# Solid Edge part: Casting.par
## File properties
Author: Deepak Maini
Template: Normal.par
Last saved by: CADCIM
Revision: 10
Application: Solid Edge
Accuracy: 0.99
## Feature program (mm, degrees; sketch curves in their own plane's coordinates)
sketch for "unnamed Protrusion 1" plane through (0, 0, 0) normal (0, -1, 0) x-axis (1, 0, 0)
  line (0, 0) -> (0, 0)
  line (-104, 0) -> (104, 0)
  line (104, 0) -> (100, 14)
  line (100, 14) -> (-100, 14)
  line (-100, 14) -> (-104, 0)
  dimension (linear) = 104
  dimension (linear) = 104
extrude "unnamed Protrusion 1" add finite 46 symmetric
sketch for "ExtrudedProtrusion_2" plane through (0, 0, 0) normal (0, 0, 1) x-axis (1, 0, 0)
  line (-48.8569, 23) -> (48.8569, 23)
  arc centre (0, 0) radius 54 from (48.8569, 23) to (48.8569, -23) cw
  line (-48.8569, -23) -> (48.8569, -23)
  arc centre (0, 0) radius 54 from (-48.8569, -23) to (-48.8569, 23) cw
extrude "ExtrudedProtrusion_2" add finite 68 along +normal
sketch for "ExtrudedCutout_1" plane through (0, 0, 0) normal (0, -1, 0) x-axis (1, 0, 0)
  line (24, 52) -> (24, 48)
  line (28, 52) -> (24, 52)
  line (28, 68) -> (28, 52)
  line (-28, 68) -> (28, 68)
  line (-28, 52) -> (-28, 68)
  line (-24, 52) -> (-28, 52)
  line (-24, 48) -> (-24, 52)
  arc centre (0, 48) radius 24 from (24, 48) to (-24, 48) cw
extrude "ExtrudedCutout_1" cut finite 46 symmetric
chamfer "Chamfer_1" setback 2
fillet "Round_1" radius 8
sketch for "Hole_1" plane through (-41, 0, 68) normal (0, 0, 1) x-axis (0, 1, 0)
  hole centre (0, -80) bore radius 6
hole "Hole_1" diameter 12 through
sketch for "ExtrudedCutout_2" plane through (0, 0, 0) normal (0, 0, 1) x-axis (1, 0, 0)
  line (23.9671, 14) -> (23.9671, -14)
  line (23.9671, -14) -> (51.9671, -14)
  line (51.9671, -14) -> (51.9671, 14)
  line (51.9671, 14) -> (23.9671, 14)
extrude "ExtrudedCutout_2" cut finite 12 along +normal
sketch for "unnamed Cutout 1" plane through (0, 0, 0) normal (0, 0, 1) x-axis (1, 0, 0)
  line (71, 6) -> (71, -6)
  line (71, -6) -> (91, -6)
  line (91, -6) -> (91, 6)
  line (91, 6) -> (71, 6)
extrude "unnamed Cutout 1" cut through along +normal
fillet "Round_2" radius 6
mirror "unnamed Mirror 1" of "Round_2", "unnamed Cutout 1", "ExtrudedCutout_2", "Hole_1"
pattern "unnamed Pattern 1"
sketch for "ExtrudedCutout_4" plane through (0, 0, 0) normal (0, 0, 1) x-axis (1, 0, 0)
  line (-97.5, 20) -> (-97.5, -20)
  line (-97.5, -20) -> (97.5, -20)
  line (97.5, -20) -> (97.5, 20)
  line (97.5, 20) -> (-97.5, 20)
extrude "ExtrudedCutout_4" cut finite 2 along +normal
sketch for "Hole_3" plane through (-41, 0, 68) normal (0, 0, 1) x-axis (1, 0, 0)
  hole centre (41, 0) bore radius 4
hole "Hole_3" diameter 8 finite
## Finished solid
Body 1: solid body, 53 faces, 134 edges, 84 vertices.
  Faces by surface: plane 39, cylinder 10, cone 2, torus 2
  Edges by curve: line 106, circle 23, intersection 5
Bounding box of the edges (mm; curved faces can reach further): 208.000 x 46.000 x 68.000, from (-104, -23, 0) to (104, 23, 68).
Cylindrical faces by radius (mm): R4 x1, R6 x6, R24 x1, R54 x2
Conical faces (half-angle, radius in mm at the cone's reference point): 45 deg R24 x1, 45 deg R26 x1
Toroidal faces (ring radius, tube radius in mm): R62 r8 x2
Planar faces by outward normal: +x 5, +y 6, +z 7, -x 5, -y 6, -z 4, oblique 6
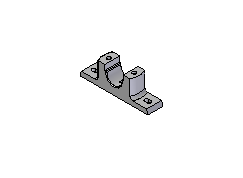
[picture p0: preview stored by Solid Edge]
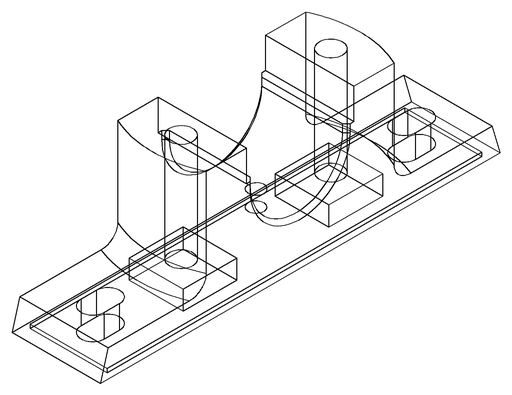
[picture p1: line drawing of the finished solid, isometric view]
